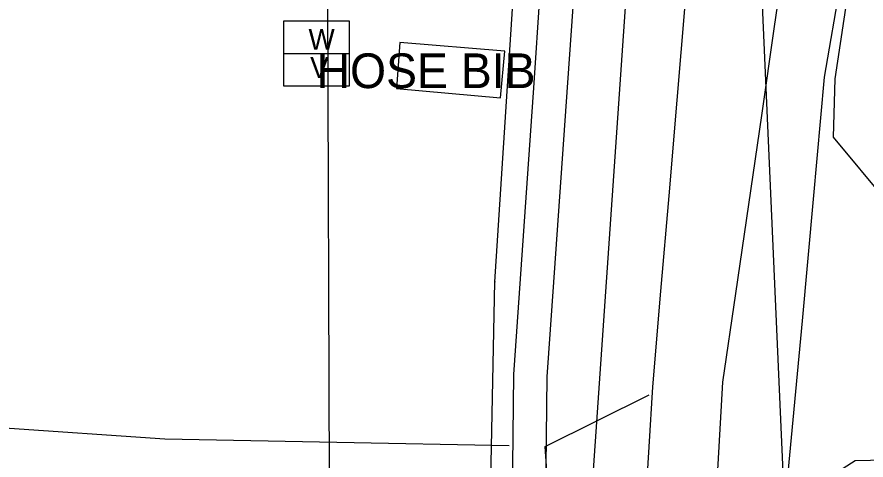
# Model space of a CAD drawing. Extents: x 997398 to 1003416, y 334596 to 337085.
# Drawn here: x 999151.8 to 999274.2, y 335481.5 to 335545.4 of the extents above; entities that cross this region are included whole.
import ezdxf

# ---------------------------------------------------------------- set-up
doc = ezdxf.new("R2010")
doc.units = 0
for name, color, linetype in [('Default', 7, 'Continuous'), ('S_DRIVEWAY', 7, 'Continuous'), ('S_EDGE_CONCRETE', 7, 'Continuous'), ('S_EDGE_PAVEMENT', 7, 'Continuous'), ('S_GAS_UTILITIES', 7, 'Continuous'), ('S_GRAVEL_ROAD', 7, 'Continuous'), ('S_PAVEMENT_CROWN', 7, 'Continuous'), ('S_SANITARY_SEWER', 7, 'Continuous'), ('S_SIDE_DRAIN', 7, 'Continuous'), ('S_SIDEWALK', 7, 'Continuous'), ('S_UTL_PT_SYM', 7, 'Continuous'), ('S_WATER_UTILITIES', 7, 'Continuous'), ('S_WATER_UTILITIES_ANNOT', 7, 'Continuous')]:
    doc.layers.add(name, color=color, linetype=linetype)

msp = doc.modelspace()

# ---------------------------------------------------------------- linework, layer by layer
at = {"layer": 'Default'}
msp.add_line((999272.07, 335256.17), (999254.77, 335651.12), dxfattribs=at)
at = {"layer": 'S_DRIVEWAY'}
msp.add_lwpolyline([(999240.62, 335452.32), (999234.74, 335458.11), (999228.93, 335458.39), (999229.26, 335464.28), (999227.96, 335483.47), (999242.96, 335490.88)], dxfattribs=at)
at = {"layer": 'S_EDGE_CONCRETE'}
for points in [[(999207.03, 335541.71), (999206.55, 335535.05), (999221.51, 335533.71), (999222.15, 335540.42)], [(999222.15, 335540.42), (999207.03, 335541.71)]]:
    msp.add_lwpolyline(points, dxfattribs=at)
at = {"layer": 'S_EDGE_PAVEMENT'}
for points in [[(999242.46, 335474.78), (999243.48, 335492.06), (999244.65, 335505.83), (999245.83, 335519.59), (999247.01, 335533.36), (999248.18, 335547.12), (999246.58, 335559.54), (999244.98, 335571.95), (999238.35, 335581.43), (999223.76, 335588.45), (999204.45, 335589.72), (999185.14, 335591), (999163.46, 335592.01), (999141.78, 335593.03), (999120.82, 335594.21), (999099.85, 335595.38), (999086.61, 335596.71), (999073.36, 335598.03)], [(999250.53, 335290.61), (999251.9, 335310.31), (999253.28, 335330), (999254.66, 335349.69), (999256.03, 335369.39), (999256.96, 335383.69), (999257.89, 335397.99), (999259.31, 335422.72), (999260.17, 335436.32), (999261.04, 335449.92), (999261.9, 335463.52), (999262.77, 335477.12), (999265.06, 335501.55), (999266.67, 335519.12), (999268.27, 335536.68), (999270.61, 335550.38), (999272.95, 335564.07), (999275.29, 335577.76), (999277.63, 335591.45)], [(999268.87, 335320.6), (999263.53, 335329.26), (999260.4, 335340), (999260.03, 335350.15), (999261.25, 335369.32), (999262.19, 335383.58), (999263.12, 335397.84), (999266.91, 335402.13), (999261.38, 335422.51), (999262.14, 335435.92), (999262.89, 335449.33), (999263.64, 335462.75), (999264.4, 335476.16), (999272.66, 335481.44), (999281.46, 335481.65), (999283.33, 335495.44), (999285.2, 335509.23), (999269.56, 335528.03), (999269.81, 335536.47), (999271.83, 335550.21), (999273.84, 335563.95), (999275.86, 335577.69), (999277.88, 335591.43)]]:
    msp.add_lwpolyline(points, dxfattribs=at)
at = {"layer": 'S_GAS_UTILITIES'}
for p, q in [((999220.7, 335507.17), (999223.28, 335546.56)), ((999219.71, 335459.22), (999220.7, 335507.17))]:
    msp.add_line(p, q, dxfattribs=at)
at = {"layer": 'S_GRAVEL_ROAD'}
msp.add_lwpolyline([(999073.86, 335562.63), (999072.4, 335541.59), (999070.94, 335520.55), (999081.52, 335511), (999092.11, 335501.46), (999108.75, 335494.65), (999125.4, 335487.85), (999149.27, 335486.2), (999173.14, 335484.55), (999197.95, 335484.07), (999222.77, 335483.59)], dxfattribs=at)
at = {"layer": 'S_PAVEMENT_CROWN'}
msp.add_lwpolyline([(999240.93, 335269.15), (999242.42, 335292.45), (999243.36, 335312.31), (999244.3, 335332.17), (999245.73, 335356.52), (999247.17, 335380.88), (999248.33, 335401.35), (999249.49, 335421.83), (999250.52, 335439.55), (999251.54, 335457.27), (999252.57, 335474.99), (999253.6, 335492.71), (999255.46, 335505.53), (999257.33, 335518.35), (999259.19, 335531.16), (999261.06, 335543.98), (999262.92, 335556.8), (999264.79, 335569.61), (999266.65, 335582.43), (999268.52, 335595.25), (999272.87, 335613.5), (999277.22, 335631.74), (999281.77, 335646.2)], dxfattribs=at)
at = {"layer": 'S_SANITARY_SEWER'}
msp.add_line((999197.31, 335352.9), (999196.62, 335551), dxfattribs=at)
at = {"layer": 'S_SIDE_DRAIN'}
msp.add_line((999233.26, 335456.06), (999241.18, 335570.41), dxfattribs=at)
at = {"layer": 'S_SIDEWALK'}
for points in [[(999214.01, 335280.58), (999214.8, 335292.62), (999216.16, 335313.46), (999217.52, 335334.3), (999218.07, 335347.06), (999218.63, 335359.82), (999222.21, 335371.88), (999225.78, 335383.94), (999224.2, 335403.9), (999222.62, 335423.86), (999222.83, 335441.35), (999223.04, 335458.84), (999223.26, 335476.33), (999223.47, 335493.82), (999224.42, 335507.61), (999225.37, 335521.4), (999226.32, 335535.18), (999227.27, 335548.97)], [(999225.73, 335271.38), (999218.89, 335281.67), (999219.66, 335292.48), (999220.98, 335313.22), (999222.31, 335333.97), (999223.3, 335346.79), (999224.29, 335359.6), (999230.64, 335383.76), (999229.05, 335404.13), (999227.47, 335424.5), (999227.67, 335441.74), (999227.86, 335458.99), (999228.06, 335476.23), (999228.26, 335493.48), (999229.22, 335507.16), (999230.18, 335520.85), (999231.14, 335534.54), (999232.1, 335548.22)]]:
    msp.add_lwpolyline(points, dxfattribs=at)
at = {"layer": 'S_UTL_PT_SYM'}
msp.add_lwpolyline([(999220.7, 335507.17), (999220.7, 335507.22), (999220.7, 335507.17), (999220.65, 335507.17), (999220.7, 335507.17), (999220.7, 335507.12), (999220.7, 335507.17), (999220.75, 335507.17)], dxfattribs=at)
at = {"layer": 'S_WATER_UTILITIES'}
for p, q in [((999190.29, 335544.81), (999199.71, 335544.81)), ((999190.29, 335535.4), (999190.29, 335544.81)), ((999199.71, 335544.81), (999199.71, 335535.4)), ((999190.29, 335540.12), (999199.71, 335540.12)), ((999199.71, 335535.4), (999190.29, 335535.4))]:
    msp.add_line(p, q, dxfattribs=at)

# ---------------------------------------------------------------- texts
for s, p in [('W', (999193.84, 335540.65)), ('V', (999194.08, 335536.59))]:
    msp.add_text(s, height=3, rotation=360, dxfattribs=at).set_placement(p)
at = {"layer": 'S_WATER_UTILITIES_ANNOT'}
msp.add_text('HOSE BIB', height=5, dxfattribs=at).set_placement((999195, 335535.12))

doc.saveas('drawing.dxf')
